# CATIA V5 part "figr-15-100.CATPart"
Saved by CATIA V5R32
Part number: Part1
Bounding box of the stored display mesh (mm): x -52.43 to 60.529, y -25.631 to 32.893, z 0 to 4
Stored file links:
  D:\PROJECTS\Project 2022\CATIA V5 6R 2022\Resources\Part Files\c15_catia_v5_6r2022_prt\figr-15-100.CATPart
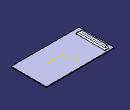
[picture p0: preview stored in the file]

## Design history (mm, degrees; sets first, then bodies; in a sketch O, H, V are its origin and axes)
SheetMetalParameters1: Thickness 1, BendRadius 5, KFactor 0.5 {= log(min(100,max(20*SheetMetalParameters1.BendRadius,SheetMetalParameters1.Thickness)/SheetMetalParameters1.Thickness))/log(100)/2}, ReliefRadialLength 1, ReliefAxialLength 2, MinimumBendRadius 0
Body1 (main body)
  Sketch1 on xy-plane, origin (0, 0, 0), H (1, 0, 0), V (0, 1, 0)
    line L1 (-52.4297, 32.8934) -> (60.5286, 32.8934)
    line L2 (60.5286, 32.8934) -> (60.5286, -25.6312)
    line L3 (60.5286, -25.6312) -> (-52.4297, -25.6312)
    line L4 (-52.4297, -25.6312) -> (-52.4297, 32.8934)
    horizontal: L1 H, L3 H
    vertical: L2 V, L4 V
  Wall1: Thickness 1, Profile Sketch1
  Sketch2 on face of Wall1, origin (0, 0, 1), H (1, 0, 0), V (0, 1, 0)
    line L1 (-47.3159, -16.5837) -> (-43.073, -16.5837)
    line L2 (-43.073, -16.5837) -> (-43.073, 26.788)
    line L3 (-43.073, 26.788) -> (-47.3159, 26.788)
    line L4 (-47.3159, 26.788) -> (-47.3159, -16.5837)
    horizontal: L1 H, L3 H
    vertical: L2 V, L4 V
  d_Stamp1: Stamp_FilletRadius 2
